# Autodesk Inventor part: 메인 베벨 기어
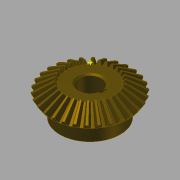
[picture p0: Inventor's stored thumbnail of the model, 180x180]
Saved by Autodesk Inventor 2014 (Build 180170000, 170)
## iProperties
Created: 2014-10
Part Number: 메인 베벨 기어
Material: 강철, 탄소
Document SubType Name: Modeling
Designer: KYOUNG IL JANG
Categories: <?xml version="1.0" encoding="UTF-16"?> <MemberInstance><Categories><FamilyTemplate><FamilyTemplateParameter ValueType="xs:double" Id="1" ObjectReferenceKey="da
Mass: 269.926 g
Surface Area: 108.837 cm^2
Volume: 34.2981 cm^3
Density: 7.87 g/cm^3
Appearance: 얼룩무늬
CustomPartVersion: 1
da_b: 14.400 mm
da_de: 60.000 mm
da_dae: 62.219 mm
da_dfe: 57.337 mm
da_le: 36.056 mm
da_omega: 90.00 deg
da_beta: 0.00 deg
da_delta: 56.31 deg
da_alpha: 20.00 deg
da_he: 4.400 mm
da_ve: 18.336 mm
da_z: 30.000 ul
da_z2: 20.000 ul
fd_dv: 108.167 mm
fd_dva: 112.167 mm
fd_dvb: 101.643 mm
da_zv: 54.083 ul
fd_loft: 14.620 mm
fd_ratio: 0.596 ul
fd_rr: 19.188 mm
fd_angle: 1.68 deg
fd_x1: 1.588 mm
fd_y1: 54.060 mm
fd_x2: 17.869 mm
fd_y2: 6.991 mm
fd_x: 19.457 mm
fd_y: 47.069 mm
fd_angle2: 19.68 deg
fd_dd: 108.647 mm
da_dvw: 108.167 mm
da_dm: 48.018 mm
da_x: 0.000 ul
da_m: 2.000 mm
da_teethtype: 0.000 ul
d56: 10.373 mm
d0: 60.000 mm
d1: 57.337 mm
d2: 62.219 mm
d3: 14.400 mm
d4: 18.336 mm
d7: 19.188 mm
d8: 19.457 mm
d9: 47.069 mm
d11: 14.620 mm
d12: 11.427 mm
d15: 11.587 mm
d16: 28.030 mm
d17: 0.000 ul
d18: 90.00 deg
d19: 0.000 ul
d20: 90.00 deg
d21: 30.000 ul
d22: 360.00 deg
d26: 229.906 mm
d27: 8.110 mm
d28: 60.000 mm
d29: -56.31 deg
d30: 11.427 mm
d31: 11.587 mm
d32: 28.030 mm
d35: 0.000 ul
d37: 0.000 ul
d39: 0.000 ul
d40: 90.00 deg
d41: 30.000 ul
d42: 360.00 deg
d48: 0.000 mm
d49: 0.000 mm
d50: 90.00 deg
d51: 6.00 deg
d52: 0.000 mm
d53: 0.000 mm
d54: 0.00 deg
d57: 57.403 mm
d58: 51.155 mm
d59: 34.184 mm
d60: 30.464 mm
d61: 34.184 mm
d62: 30.464 mm
d65: 229.906 mm
d66: 3.150 ul
d67: 60.000 mm
d68: -56.31 deg
d69: 8.110 mm
d70: 11.587 mm
d71: 28.030 mm
d72: 11.427 mm
d73: 30.464 mm
d74: 34.184 mm
d75: 0.000 ul
d77: 0.000 ul
d79: 0.000 ul
d80: 90.00 deg
d81: 30.000 ul
d82: 360.00 deg
d84: 1.000 ul
d85: 2.000 ul
d86: 2.000 ul
d87: 1.000 ul
d88: 0.000 ul
d89: 0.000 ul
d90: 90.00 deg
d91: 90.00 deg
d92: 90.00 deg
d93: 90.00 deg
d94: 45.000 mm
d95: 13.000 mm
d96: 0.00 deg
d97: 17.000 mm
d104: 5.000 mm
d107: 0.00 deg
d108: 1.000 mm
d111: 2.000 mm
d112: 19.300 mm
Author: SeoGD™ [www.esajin.kr]
Revision Number: 1
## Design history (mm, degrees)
node "맨 위 점"
node "메쉬 평면2"
sketch "톱니 본체 스케치"
  geometry: L1 (0, 0)-(28.669, -21.997); L2 (28.669, -21.997)-(31.109, -18.336); L3 (31.109, -18.336)-(0, 0); L4 (30, -20)-(0, 0); L5 (17.219, -13.212)-(18.685, -11.013); L6 (28.669, -21.997)-(17.219, -13.212); L7 (31.109, -18.336)-(18.685, -11.013); L8 (0, -39.387)-(0, 6.564) reference; L9 (0, -20)-(31.109, -20)
  constraints: 16 end point, 4 point on line, 3 perpendicular, 2 collinear, 1 horizontal alignment, 1 vertical alignment
  dimensions: "d0" = 60 diameter of L4.start L8 (= da_de); "d1" = 57.33744 diameter of L1.end L8 (= da_dfe); "d2" = 62.2188 diameter of L2.end L8 (= da_dae); "d3" = 14.4 distance between parallel lines of L2 L5 (= da_b); "d4" = 18.3359 vertical distance of L2.end L1.start (= da_ve)
revolve "톱니 본체" sketch "톱니 본체 스케치" stored, may be unused: angle "d5" = 90 deg
node "시작점"
node "톱니 평면"
sketch "시작 스케치"
  geometry: L1 (0, -23.505)-(0, 10.645) reference; L2 (-0.709, -2.928)-(0.709, -2.928); A1 r 19.188 centre (-19.457, -7.014) between (-0.709, -2.928) and (-3.232, 3.229); A2 r 19.188 centre (19.457, -7.014) between (3.232, 3.229) and (0.709, -2.928); A3 r 57.403 centre (0, -54.083) between (3.232, 3.229) and (-3.232, 3.229); 1 further point
  constraints: 6 point on circle, 3 centre point, 3 symmetric about line, 2 end point, 1 coincident, 1 perpendicular, 1 other
  dimensions: "d7" = 19.18795 radius of A1 (= fd_rr); "d8" = 19.45712 horizontal distance of point (0, -54.083) A1.centre (= fd_x); "d9" = 47.06905 vertical distance of point (0, -54.083) A1.centre (= fd_y); "d57" = 57.40327 radius of A3 (= 0.5 x fd_dva + 0.3 x da_he); "d58" = 51.15527 distance from line of A3.centre L2 (= 0.5 x fd_dva - 1.12 x da_he)
node "끝점"
  node "끝 평면"
sketch "3D 스케치 오른쪽"
  node "Helical Curve Right" dims "d65" = 229.90621 (computed from da_dm, da_delta, da_beta), count "d66" = 3.15, "d67" = 60 (= da_de), angle "d68" = -56.3099 deg (= -da_delta), "d69" = 8.10972 (computed from fd_loft, da_delta)
node "끝 평면 오른쪽"
sketch "끝 스케치 오른쪽"
  geometry: L1 (0, -41.54)-(0, 13.178) reference; L2 (-0.422, -1.69)-(0.422, -1.69); A1 r 11.427 centre (-11.587, -4.123) between (-0.422, -1.69) and (-1.925, 1.977); A2 r 11.427 centre (11.587, -4.123) between (1.925, 1.977) and (0.422, -1.69); A3 r 34.184 centre (0, -32.153) between (1.925, 1.977) and (-1.925, 1.977); 1 further point
  constraints: 6 point on circle, 3 centre point, 3 symmetric about line, 2 end point, 1 coincident, 1 perpendicular, 1 other
  dimensions: "d70" = 11.58699 horizontal distance of A3.centre A1.centre (computed from fd_x, fd_ratio); "d71" = 28.03028 vertical distance of point (0, -32.153) A1.centre (computed from fd_y, fd_ratio); "d72" = 11.4267 radius of A1 (computed from fd_rr, fd_ratio); "d73" = 30.46369 distance from line of point (0, -32.153) L2 (computed from d58, fd_ratio); "d74" = 34.18446 radius of A3 (computed from d57, fd_ratio)
feature "로프트 오른쪽" sketch "끝 스케치 오른쪽" dims count "d75" = 0, count "d77" = 0, count "d79" = 0, angle "d80" = 90 deg, count "d85" = 2, angle "d92" = 90 deg, angle "d93" = 90 deg, count "da_teethtype" = 0 [user parameter]
sketch "3D 스케치 왼쪽"
  node "Helical Curve Left" dims "d26" = 229.90621 (computed from da_dm, da_delta, da_beta), "d27" = 8.10972 (computed from fd_loft, da_delta), "d28" = 60 (= da_de), angle "d29" = -56.3099 deg (= -da_delta)
node "끝 평면 왼쪽"
sketch "끝 스케치 왼쪽" dims "d56" = 10.3728 (derived)
  geometry: L1 (0, -43.753)-(0, 15.405) reference; L2 (-0.422, -1.678)-(0.422, -1.678); A1 r 11.427 centre (-11.587, -4.111) between (-0.422, -1.678) and (-1.925, 1.988); A2 r 11.427 centre (11.587, -4.111) between (1.925, 1.988) and (0.422, -1.678); A3 r 34.184 centre (0, -32.142) between (1.925, 1.988) and (-1.925, 1.988); 2 further points; 1 other entity
  constraints: 6 point on circle, 3 centre point, 3 symmetric about line, 2 end point, 1 coincident, 2 other
  dimensions: "d30" = 11.4267 radius of A1 (computed from fd_rr, fd_ratio); "d31" = 11.58699 horizontal distance of point (0, -32.142) A1.centre (computed from fd_x, fd_ratio); "d32" = 28.03028 vertical distance of A1.centre point (0, -32.142) (computed from fd_y, fd_ratio); "d61" = 34.18446 radius of A3 (computed from d57, fd_ratio); "d62" = 30.46369 distance from line of point (0, -32.142) L2 (computed from d58, fd_ratio)
feature "로프트 왼쪽" sketch "끝 스케치 왼쪽" dims count "d35" = 0, count "d37" = 0, count "d39" = 0, angle "d40" = 90 deg, count "d84" = 1, angle "d90" = 90 deg, angle "d91" = 90 deg, count "da_teethtype" = 0 [user parameter]
sketch "본체 스케치"
  geometry: L1 (0, -35.038)-(0, -19.531) reference; L2 (28.669, -21.997)-(17.219, -13.212) reference; L3 (17.219, -13.212)-(0, -13.212); L4 (28.669, -21.997)-(0, -21.997)
  constraints: 4 end point, 2 perpendicular, 2 point on line
revolve "본체 고정" sketch "본체 스케치" stored, may be unused: angle "d46" = 90 deg
feature "피치 지름" dims angle "d47" = 90 deg
sketch "스케치8"
  geometry: C1 r 22.5 at (0, 0); 1 further point
  constraints: 1 centre point, 1 coincident
  dimensions: "d94" = 45 diameter of C1
extrude "돌출1" join sketch "스케치8" distance "d95" = 13; taper "d96" = 0 deg
sketch "스케치9"
  geometry: 1 further point
hole "구멍1" sketch "스케치9" at (0, 0) diameter "d97" = 17; stored, may be unused: countersink angle "d101" = 90 deg, drill point angle "d103" = 118 deg; dims "d98" = 6, "d99" = 4, "d100" = 2, "d102" = 8
sketch "스케치10"
  geometry: L1 (8.124, 2.5)-(10.8, 2.5); L2 (10.8, 2.5)-(10.8, -2.5); L3 (10.8, -2.5)-(8.124, -2.5); A1 r 8.5 centre (0, 0) between (8.124, 2.5) and (8.124, -2.5) reference; 1 further point
  constraints: 6 end point, 2 parallel, 2 point on circle, 1 horizontal, 1 perpendicular
  dimensions: "d104" = 5 distance of L1.end L2.end; "d112" = 19.3 dimension on A1 L2
extrude "돌출2" cut sketch "스케치10" stored distance "d106" = 10; taper "d107" = 0 deg
chamfer "모따기1" distance "d108" = 1; stored, may be unused: second distance "d109" = 2, angle "d110" = 45 deg
fillet "모깎기1" dims "d111" = 2
body "Solid1"
feature "로프트" dims count "d17" = 0, angle "d18" = 90 deg, count "d19" = 0, angle "d20" = 90 deg, count "d89" = 0, count "da_teethtype" = 0 [user parameter]
pattern_circular "원형 패턴" dims count "d21" = 30 (= da_z), angle "d22" = 360 deg, count "d88" = 0, count "da_teethtype" = 0 [user parameter]
pattern_circular "원형 패턴 오른쪽" dims count "d81" = 30 (= da_z), angle "d82" = 360 deg, count "d86" = 2, count "da_teethtype" = 0 [user parameter]
pattern_circular "원형 패턴 왼쪽" dims count "d41" = 30 (= da_z), angle "d42" = 360 deg, count "d87" = 1, count "da_teethtype" = 0 [user parameter]
sketch "끝 스케치"
  geometry: L1 (0, -15.359)-(0, 6.983) reference; L2 (-0.422, -1.69)-(0.422, -1.69); A1 r 11.427 centre (-11.587, -4.123) between (-0.422, -1.69) and (-1.925, 1.977); A2 r 11.427 centre (11.587, -4.123) between (1.925, 1.977) and (0.422, -1.69); A3 r 34.184 centre (0, -32.153) between (1.925, 1.977) and (-1.925, 1.977); 1 further point
  constraints: 6 point on circle, 3 centre point, 3 symmetric about line, 2 end point, 1 coincident, 1 other
  dimensions: "d12" = 11.4267 radius of A1 (computed from fd_rr, fd_ratio); "d15" = 11.58699 horizontal distance of A1.centre point (0, -32.153) (computed from fd_x, fd_ratio); "d16" = 28.03028 vertical distance of A1.centre point (0, -32.153) (computed from fd_y, fd_ratio); "d59" = 34.18446 radius of A3 (computed from d57, fd_ratio); "d60" = 30.46369 distance from line of A3.centre L2 (computed from d58, fd_ratio)
sketch "Sketch6"
  geometry: L1 (30, -20)-(0, 0) reference; L2 (0, -37.8)-(0, 6.3) reference
body "Srf1"
other parameters: "da_b" = 14.4 [user parameter; used in 2 equation terms], "da_de" = 60 [user parameter; used in 4 equation terms], "da_dae" = 62.2188 [user parameter; used in 2 equation terms], "da_dfe" = 57.33744 [user parameter; used in 1 equation term], "da_le" = 36.05551 [user parameter; used in 1 equation term], "da_omega" = 90 deg [user parameter; used in 1 equation term], "da_beta" = 0 deg [user parameter; used in 2 equation terms], "da_delta" = 56.3099 deg [user parameter; used in 8 equation terms], "da_alpha" = 20 deg [user parameter; used in 2 equation terms], "da_he" = 4.4 [user parameter; used in 4 equation terms], "da_ve" = 18.3359 [user parameter; used in 1 equation term], "da_z" = 30 [user parameter; used in 4 equation terms], "da_z2" = 20 [user parameter], "fd_dv" = 108.16654 (computed from da_de, da_delta) [user parameter; used in 1 equation term], "fd_dva" = 112.16654 (computed from da_dae, da_delta) [user parameter; used in 3 equation terms], "fd_dvb" = 101.6433 (computed from fd_dv, da_alpha) [user parameter; used in 2 equation terms], "da_zv" = 54.0833 [user parameter; used in 1 equation term], "fd_loft" = 14.62 (= da_b + 0.05 x da_he) [user parameter; used in 4 equation terms], "fd_ratio" = 0.595514 (computed from da_le, fd_loft) [user parameter; used in 15 equation terms], "fd_rr" = 19.18795 (computed from fd_dd, fd_dvb) [user parameter; used in 6 equation terms], "fd_angle" = 1.68259 deg (computed from da_zv) [user parameter; used in 4 equation terms], "fd_x1" = 1.58802 (computed from da_dvw, fd_angle) [user parameter; used in 1 equation term], "fd_y1" = 54.05995 (computed from da_dvw, fd_angle) [user parameter; used in 1 equation term], "fd_x2" = 17.8691 (computed from fd_rr, fd_angle2, fd_angle) [user parameter; used in 1 equation term], "fd_y2" = 6.9909 (computed from fd_rr, fd_angle2, fd_angle) [user parameter; used in 1 equation term], "fd_x" = 19.45712 (= fd_x1 + fd_x2) [user parameter; used in 4 equation terms], "fd_y" = 47.06905 (= fd_y1 - fd_y2) [user parameter; used in 4 equation terms], "fd_angle2" = 19.6843 deg (computed from fd_dvb, fd_dd, da_alpha) [user parameter; used in 2 equation terms], "fd_dd" = 108.64654 (= fd_dva - 0.8 x da_he) [user parameter; used in 2 equation terms], "da_dvw" = 108.16654 [user parameter; used in 2 equation terms], "d11" = 14.62 (= fd_loft), "da_dm" = 48.01848 [user parameter; used in 2 equation terms], "da_x" = 0 [user parameter], "da_m" = 2 [user parameter], "d48" = 0, "d49" = 0, "d50" = 90 deg (= da_omega), "d51" = 6 deg (computed from da_z), "d52" = 0, "d53" = 0, "d54" = 0 deg
